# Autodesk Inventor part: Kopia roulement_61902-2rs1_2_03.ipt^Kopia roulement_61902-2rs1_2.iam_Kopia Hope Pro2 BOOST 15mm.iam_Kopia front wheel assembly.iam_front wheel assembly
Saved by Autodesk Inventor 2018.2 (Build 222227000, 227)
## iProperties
Created: 2017-09
Part Number: Kopia roulement_61902-2rs1_2_03.ipt^Kopia roulement_61902-2rs1_2.iam_Kopia Hope Pro2 BOOST 15mm.iam_Kopia front wheel assembly.iam_front wheel assembly
Material: Ogólny
Document SubType Name: Modeling
Designer: Tomasz
Density: 1 g/cm^3
Appearance: Domyślna
Author: Tomasz
Sending System: SolidWorks 2017
Last Author: Tomasz
Last Saved: 2017-09-11
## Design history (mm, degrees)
